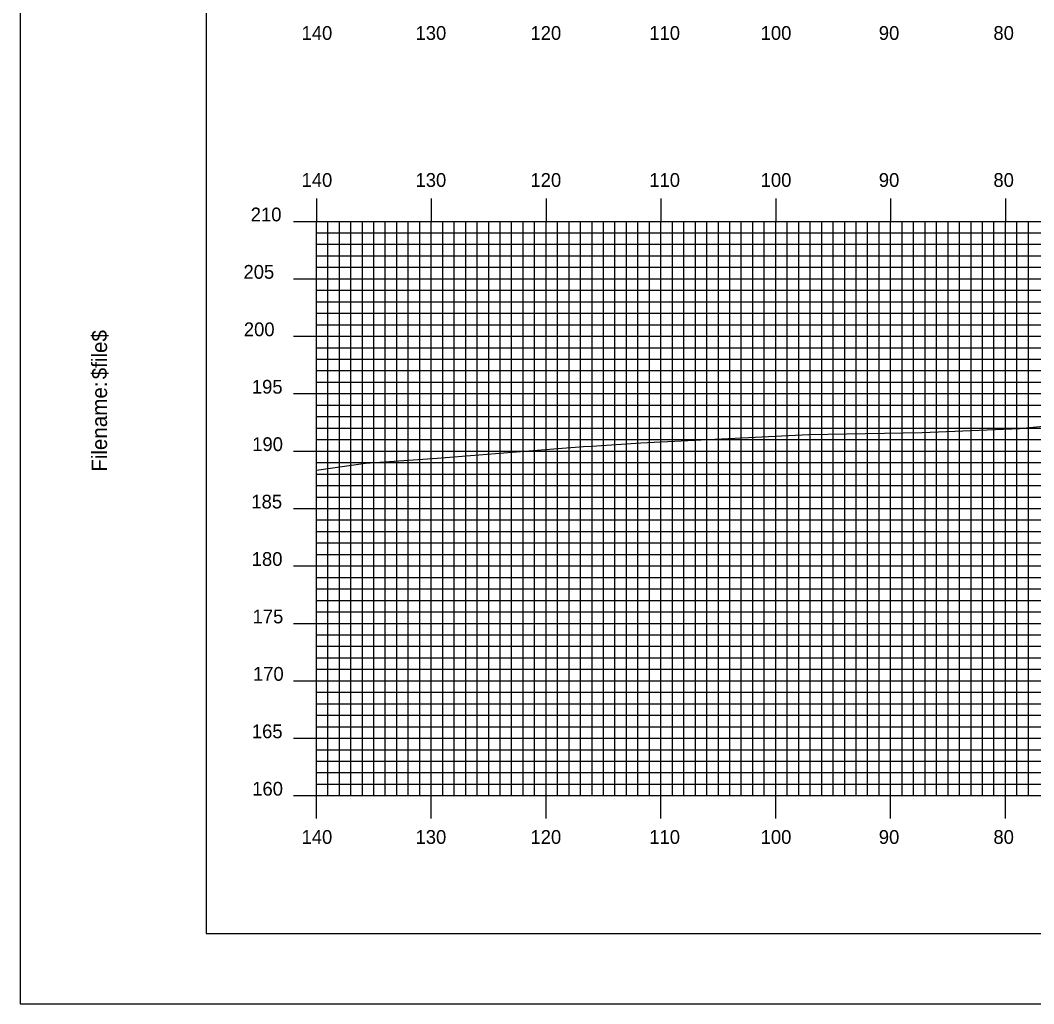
# Model space of a CAD drawing. Extents: x 1794846 to 1795189, y 442591 to 442811.
# Drawn here: x 1794846.1 to 1794934.3, y 442590.5 to 442676.2 of the extents above; entities that cross this region are included whole.
import ezdxf

# ---------------------------------------------------------------- set-up
doc = ezdxf.new("R2010")
doc.units = 0
for name, color, linetype in [('BORDER', 7, 'Continuous'), ('H_V ANNOTATION', 7, 'Continuous'), ('MAJOR', 7, 'Continuous'), ('MINOR', 7, 'Continuous'), ('PLOT BOUNDARY', 7, 'Continuous'), ('S_Roadway_Centerline', 7, 'Continuous')]:
    doc.layers.add(name, color=color, linetype=linetype)

msp = doc.modelspace()

# ---------------------------------------------------------------- linework, layer by layer
at = {"layer": 'BORDER'}
msp.add_lwpolyline([(1794862.253, 442596.665), (1795182.253, 442596.665), (1795182.253, 442806.665), (1794862.253, 442806.665)], close=True, dxfattribs=at)
at = {"layer": 'MAJOR'}
for p, q in [((1794871.853, 442660.669), (1794871.853, 442658.665)), ((1794881.853, 442660.669), (1794881.853, 442658.665)), ((1794891.853, 442660.669), (1794891.853, 442658.665)), ((1794901.853, 442660.669), (1794901.853, 442658.665)), ((1794911.853, 442660.669), (1794911.853, 442658.665)), ((1794921.853, 442660.669), (1794921.853, 442658.665)), ((1794931.853, 442660.669), (1794931.853, 442658.665)), ((1794869.849, 442658.665), (1794871.853, 442658.665)), ((1794871.853, 442658.665), (1795151.853, 442658.665)), ((1794871.853, 442608.665), (1794871.853, 442658.665)), ((1794871.853, 442608.665), (1794871.853, 442658.665)), ((1794871.853, 442658.665), (1795151.853, 442658.665)), ((1794881.853, 442608.665), (1794881.853, 442658.665)), ((1794891.853, 442608.665), (1794891.853, 442658.665)), ((1794901.853, 442608.665), (1794901.853, 442658.665)), ((1794911.853, 442608.665), (1794911.853, 442658.665)), ((1794921.853, 442608.665), (1794921.853, 442658.665)), ((1794931.853, 442608.665), (1794931.853, 442658.665)), ((1794869.849, 442653.665), (1794871.853, 442653.665)), ((1794871.853, 442653.665), (1795151.853, 442653.665)), ((1794869.849, 442648.665), (1794871.853, 442648.665)), ((1794871.853, 442648.665), (1795151.853, 442648.665)), ((1794869.849, 442643.665), (1794871.853, 442643.665)), ((1794871.853, 442643.665), (1795151.853, 442643.665)), ((1794869.849, 442638.665), (1794871.853, 442638.665)), ((1794871.853, 442638.665), (1795151.853, 442638.665)), ((1794869.849, 442633.665), (1794871.853, 442633.665)), ((1794871.853, 442633.665), (1795151.853, 442633.665)), ((1794869.849, 442628.665), (1794871.853, 442628.665)), ((1794871.853, 442628.665), (1795151.853, 442628.665)), ((1794869.849, 442623.665), (1794871.853, 442623.665)), ((1794871.853, 442623.665), (1795151.853, 442623.665)), ((1794869.849, 442618.665), (1794871.853, 442618.665)), ((1794871.853, 442618.665), (1795151.853, 442618.665)), ((1794869.849, 442613.665), (1794871.853, 442613.665)), ((1794871.853, 442613.665), (1795151.853, 442613.665)), ((1794869.849, 442608.665), (1794871.853, 442608.665)), ((1794871.853, 442608.665), (1795151.853, 442608.665)), ((1794871.853, 442608.665), (1795151.853, 442608.665)), ((1794871.853, 442606.661), (1794871.853, 442608.665)), ((1794881.853, 442606.661), (1794881.853, 442608.665)), ((1794891.853, 442606.661), (1794891.853, 442608.665)), ((1794901.853, 442606.661), (1794901.853, 442608.665)), ((1794911.853, 442606.661), (1794911.853, 442608.665)), ((1794921.853, 442606.661), (1794921.853, 442608.665)), ((1794931.853, 442606.661), (1794931.853, 442608.665))]:
    msp.add_line(p, q, dxfattribs=at)
at = {"layer": 'MINOR'}
for p, q in [((1794872.853, 442608.665), (1794872.853, 442658.665)), ((1794873.853, 442608.665), (1794873.853, 442658.665)), ((1794874.853, 442608.665), (1794874.853, 442658.665)), ((1794875.853, 442608.665), (1794875.853, 442658.665)), ((1794876.853, 442608.665), (1794876.853, 442658.665)), ((1794877.853, 442608.665), (1794877.853, 442658.665)), ((1794878.853, 442608.665), (1794878.853, 442658.665)), ((1794879.853, 442608.665), (1794879.853, 442658.665)), ((1794880.853, 442608.665), (1794880.853, 442658.665)), ((1794882.853, 442608.665), (1794882.853, 442658.665)), ((1794883.853, 442608.665), (1794883.853, 442658.665)), ((1794884.853, 442608.665), (1794884.853, 442658.665)), ((1794885.853, 442608.665), (1794885.853, 442658.665)), ((1794886.853, 442608.665), (1794886.853, 442658.665)), ((1794887.853, 442608.665), (1794887.853, 442658.665)), ((1794888.853, 442608.665), (1794888.853, 442658.665)), ((1794889.853, 442608.665), (1794889.853, 442658.665)), ((1794890.853, 442608.665), (1794890.853, 442658.665)), ((1794892.853, 442608.665), (1794892.853, 442658.665)), ((1794893.853, 442608.665), (1794893.853, 442658.665)), ((1794894.853, 442608.665), (1794894.853, 442658.665)), ((1794895.853, 442608.665), (1794895.853, 442658.665)), ((1794896.853, 442608.665), (1794896.853, 442658.665)), ((1794897.853, 442608.665), (1794897.853, 442658.665)), ((1794898.853, 442608.665), (1794898.853, 442658.665)), ((1794899.853, 442608.665), (1794899.853, 442658.665)), ((1794900.853, 442608.665), (1794900.853, 442658.665)), ((1794902.853, 442608.665), (1794902.853, 442658.665)), ((1794903.853, 442608.665), (1794903.853, 442658.665)), ((1794904.853, 442608.665), (1794904.853, 442658.665)), ((1794905.853, 442608.665), (1794905.853, 442658.665)), ((1794906.853, 442608.665), (1794906.853, 442658.665)), ((1794907.853, 442608.665), (1794907.853, 442658.665)), ((1794908.853, 442608.665), (1794908.853, 442658.665)), ((1794909.853, 442608.665), (1794909.853, 442658.665)), ((1794910.853, 442608.665), (1794910.853, 442658.665)), ((1794912.853, 442608.665), (1794912.853, 442658.665)), ((1794913.853, 442608.665), (1794913.853, 442658.665)), ((1794914.853, 442608.665), (1794914.853, 442658.665)), ((1794915.853, 442608.665), (1794915.853, 442658.665)), ((1794916.853, 442608.665), (1794916.853, 442658.665)), ((1794917.853, 442608.665), (1794917.853, 442658.665)), ((1794918.853, 442608.665), (1794918.853, 442658.665)), ((1794919.853, 442608.665), (1794919.853, 442658.665)), ((1794920.853, 442608.665), (1794920.853, 442658.665)), ((1794922.853, 442608.665), (1794922.853, 442658.665)), ((1794923.853, 442608.665), (1794923.853, 442658.665)), ((1794924.853, 442608.665), (1794924.853, 442658.665)), ((1794925.853, 442608.665), (1794925.853, 442658.665)), ((1794926.853, 442608.665), (1794926.853, 442658.665)), ((1794927.853, 442608.665), (1794927.853, 442658.665)), ((1794928.853, 442608.665), (1794928.853, 442658.665)), ((1794929.853, 442608.665), (1794929.853, 442658.665)), ((1794930.853, 442608.665), (1794930.853, 442658.665)), ((1794932.853, 442608.665), (1794932.853, 442658.665)), ((1794933.853, 442608.665), (1794933.853, 442658.665)), ((1794871.853, 442657.665), (1795151.853, 442657.665)), ((1794871.853, 442657.665), (1794873.857, 442657.665)), ((1794871.853, 442656.665), (1795151.853, 442656.665)), ((1794871.853, 442656.665), (1794873.857, 442656.665)), ((1794871.853, 442655.665), (1795151.853, 442655.665)), ((1794871.853, 442655.665), (1794873.857, 442655.665)), ((1794871.853, 442654.665), (1795151.853, 442654.665)), ((1794871.853, 442654.665), (1794873.857, 442654.665)), ((1794871.853, 442652.665), (1795151.853, 442652.665)), ((1794871.853, 442652.665), (1794873.857, 442652.665)), ((1794871.853, 442651.665), (1795151.853, 442651.665)), ((1794871.853, 442651.665), (1794873.857, 442651.665)), ((1794871.853, 442650.665), (1795151.853, 442650.665)), ((1794871.853, 442650.665), (1794873.857, 442650.665)), ((1794871.853, 442649.665), (1795151.853, 442649.665)), ((1794871.853, 442649.665), (1794873.857, 442649.665)), ((1794871.853, 442647.665), (1795151.853, 442647.665)), ((1794871.853, 442647.665), (1794873.857, 442647.665)), ((1794871.853, 442646.665), (1795151.853, 442646.665)), ((1794871.853, 442646.665), (1794873.857, 442646.665)), ((1794871.853, 442645.665), (1795151.853, 442645.665)), ((1794871.853, 442645.665), (1794873.857, 442645.665)), ((1794871.853, 442644.665), (1795151.853, 442644.665)), ((1794871.853, 442644.665), (1794873.857, 442644.665)), ((1794871.853, 442642.665), (1795151.853, 442642.665)), ((1794871.853, 442642.665), (1794873.857, 442642.665)), ((1794871.853, 442641.665), (1795151.853, 442641.665)), ((1794871.853, 442641.665), (1794873.857, 442641.665)), ((1794871.853, 442640.665), (1795151.853, 442640.665)), ((1794871.853, 442640.665), (1794873.857, 442640.665)), ((1794871.853, 442639.665), (1795151.853, 442639.665)), ((1794871.853, 442639.665), (1794873.857, 442639.665)), ((1794871.853, 442637.665), (1795151.853, 442637.665)), ((1794871.853, 442637.665), (1794873.857, 442637.665)), ((1794871.853, 442636.665), (1795151.853, 442636.665)), ((1794871.853, 442636.665), (1794873.857, 442636.665)), ((1794871.853, 442635.665), (1795151.853, 442635.665)), ((1794871.853, 442635.665), (1794873.857, 442635.665)), ((1794871.853, 442634.665), (1795151.853, 442634.665)), ((1794871.853, 442634.665), (1794873.857, 442634.665)), ((1794871.853, 442632.665), (1795151.853, 442632.665)), ((1794871.853, 442632.665), (1794873.857, 442632.665)), ((1794871.853, 442631.665), (1795151.853, 442631.665)), ((1794871.853, 442631.665), (1794873.857, 442631.665)), ((1794871.853, 442630.665), (1795151.853, 442630.665)), ((1794871.853, 442630.665), (1794873.857, 442630.665)), ((1794871.853, 442629.665), (1795151.853, 442629.665)), ((1794871.853, 442629.665), (1794873.857, 442629.665)), ((1794871.853, 442627.665), (1795151.853, 442627.665)), ((1794871.853, 442627.665), (1794873.857, 442627.665)), ((1794871.853, 442626.665), (1795151.853, 442626.665)), ((1794871.853, 442626.665), (1794873.857, 442626.665)), ((1794871.853, 442625.665), (1795151.853, 442625.665)), ((1794871.853, 442625.665), (1794873.857, 442625.665)), ((1794871.853, 442624.665), (1795151.853, 442624.665)), ((1794871.853, 442624.665), (1794873.857, 442624.665)), ((1794871.853, 442622.665), (1795151.853, 442622.665)), ((1794871.853, 442622.665), (1794873.857, 442622.665)), ((1794871.853, 442621.665), (1795151.853, 442621.665)), ((1794871.853, 442621.665), (1794873.857, 442621.665)), ((1794871.853, 442620.665), (1795151.853, 442620.665)), ((1794871.853, 442620.665), (1794873.857, 442620.665)), ((1794871.853, 442619.665), (1795151.853, 442619.665)), ((1794871.853, 442619.665), (1794873.857, 442619.665)), ((1794871.853, 442617.665), (1795151.853, 442617.665)), ((1794871.853, 442617.665), (1794873.857, 442617.665)), ((1794871.853, 442616.665), (1795151.853, 442616.665)), ((1794871.853, 442616.665), (1794873.857, 442616.665)), ((1794871.853, 442615.665), (1795151.853, 442615.665)), ((1794871.853, 442615.665), (1794873.857, 442615.665)), ((1794871.853, 442614.665), (1795151.853, 442614.665)), ((1794871.853, 442614.665), (1794873.857, 442614.665)), ((1794871.853, 442612.665), (1795151.853, 442612.665)), ((1794871.853, 442612.665), (1794873.857, 442612.665)), ((1794871.853, 442611.665), (1795151.853, 442611.665)), ((1794871.853, 442611.665), (1794873.857, 442611.665)), ((1794871.853, 442610.665), (1795151.853, 442610.665)), ((1794871.853, 442610.665), (1794873.857, 442610.665)), ((1794871.853, 442609.665), (1795151.853, 442609.665)), ((1794871.853, 442609.665), (1794873.857, 442609.665))]:
    msp.add_line(p, q, dxfattribs=at)
at = {"layer": 'PLOT BOUNDARY'}
msp.add_lwpolyline([(1794846.066, 442590.547), (1795186.066, 442590.547), (1795186.066, 442810.547), (1794846.066, 442810.547)], close=True, dxfattribs=at)
at = {"layer": 'S_Roadway_Centerline'}
msp.add_lwpolyline([(1794871.853, 442637.012), (1794876.132, 442637.598), (1794882.36, 442638.04), (1794892.538, 442638.865), (1794895.123, 442639.05), (1794895.823, 442639.097), (1794900.109, 442639.374), (1794914.735, 442640.113), (1794924.591, 442640.273), (1794933.109, 442640.62), (1794942.114, 442641.54)], dxfattribs=at)

# ---------------------------------------------------------------- texts
at = {"layer": 'BORDER'}
for s, p in [('$file$', (1794853.623, 442644.916)), ('Filename:', (1794853.623, 442636.862))]:
    msp.add_text(s, height=1.3392, rotation=90, dxfattribs=at).set_placement(p)
at = {"layer": 'H_V ANNOTATION'}
for s, p in [('140', (1794870.558, 442674.465)), ('130', (1794880.483, 442674.465)), ('120', (1794890.493, 442674.465)), ('110', (1794900.836, 442674.465)), ('100', (1794910.536, 442674.465)), ('90', (1794920.825, 442674.465)), ('80', (1794930.804, 442674.465)), ('140', (1794870.558, 442661.665)), ('130', (1794880.483, 442661.665)), ('120', (1794890.493, 442661.665)), ('110', (1794900.836, 442661.665)), ('100', (1794910.536, 442661.665)), ('90', (1794920.825, 442661.665)), ('80', (1794930.804, 442661.665)), ('210', (1794866.134, 442658.665)), ('205', (1794865.502, 442653.665)), ('200', (1794865.534, 442648.665)), ('195', (1794866.231, 442643.665)), ('190', (1794866.263, 442638.665)), ('185', (1794866.188, 442633.665)), ('180', (1794866.22, 442628.665)), ('175', (1794866.294, 442623.665)), ('170', (1794866.326, 442618.665)), ('165', (1794866.231, 442613.665)), ('160', (1794866.263, 442608.665)), ('140', (1794870.558, 442604.465)), ('130', (1794880.483, 442604.465)), ('120', (1794890.493, 442604.465)), ('110', (1794900.836, 442604.465)), ('100', (1794910.536, 442604.465)), ('90', (1794920.825, 442604.465)), ('80', (1794930.804, 442604.465))]:
    msp.add_text(s, height=1.2, dxfattribs=at).set_placement(p)
at = {"layer": 'MAJOR'}
msp.add_text('-', height=0.012, dxfattribs=at).set_placement((1794871.844, 442608.665))

doc.saveas('drawing.dxf')
